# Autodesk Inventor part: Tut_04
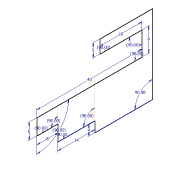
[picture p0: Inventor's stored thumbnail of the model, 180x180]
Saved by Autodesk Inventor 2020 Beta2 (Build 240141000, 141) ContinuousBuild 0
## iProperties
Created: 2019-02
Part Number: Tut_04
Material: Generic
Document SubType Name: Modeling
Designer: LENOVO-CADCIM
Density: 1 g/cm^3
Appearance: Default
Author: LENOVO-CADCIM
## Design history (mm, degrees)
sketch "Sketch1"
  geometry: L1 (0, 0)-(0, 22); L2 (0, 0)-(22, 0); L3 (0, 22)-(4, 22); L4 (4, 22)-(4, 36); L5 (4, 22)-(18, 22); L6 (4, 36)-(10, 36); L7 (10, 36)-(10, 44); L8 (10, 36)-(18, 36); L9 (10, 44)-(16, 44); L10 (16, 44)-(16, 4); L11 (16, 4)-(25, 4); L12 (25, 4)-(25, 20); L13 (25, 20)-(30, 20); L14 (30, 20)-(30, 0); L15 (30, 0)-(0, 0)
  constraints: 30 end point, 9 perpendicular, 3 horizontal, 2 vertical
  dimensions: "d0" = 90 deg angle of L2 L1; "d1" = 4 distance of L1.end L3.end; "d3" = 14 distance of L3.end L4.end; "d4" = 90 deg angle of L5 L4 (derived); "d5" = 90 deg angle of L4 L6; "d6" = 8 distance of L6.end L7.end; "d7" = 90 deg angle of L8 L7 (derived); "d8" = 6 distance of L7.end L9.end; "d9" = 90 deg angle of L7 L9 (derived); "d10" = 40 distance of L9.end L10.end; "d11" = 90 deg angle of L9 L10 (derived); "d12" = 9 distance of L10.end L11.end; "d13" = 90 deg angle of L11 L10 (derived); "d14" = 16 distance of L11.end L12.end; "d15" = 90 deg angle of L12 L11 (derived); "d16" = 5 distance of L12.end L13.end; "d17" = 90 deg angle of L12 L13 (derived)
